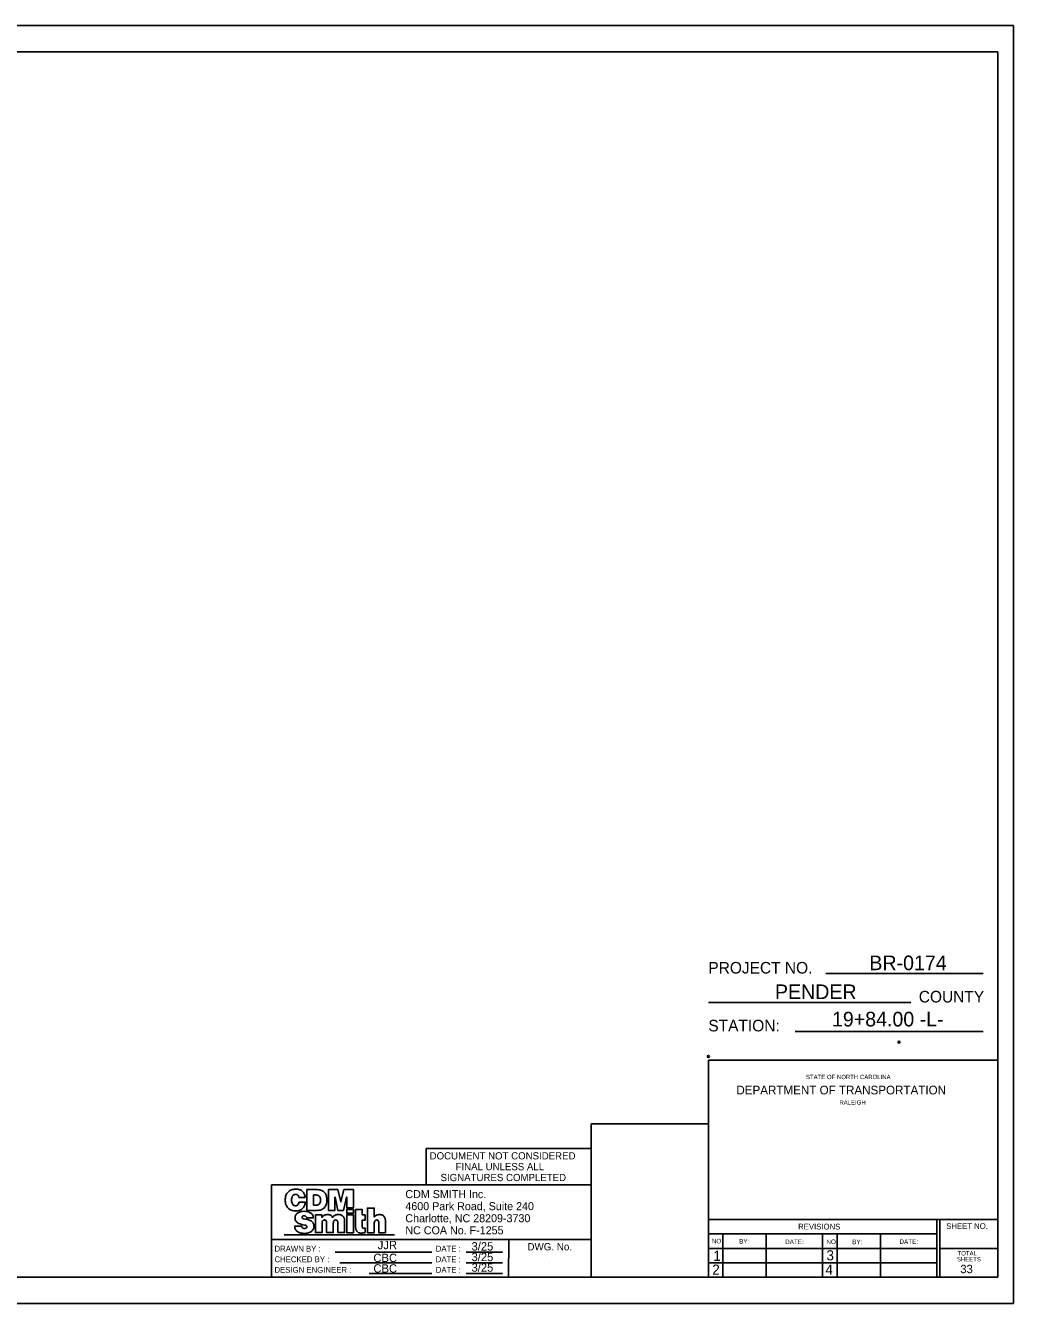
# Model space of a CAD drawing. Extents: x 0 to 2.83, y 0 to 1.83.
# Drawn here: x 1.417 to 2.833, y 0 to 1.833 of the extents above; entities that cross this region are included whole.
import ezdxf

# ---------------------------------------------------------------- set-up
doc = ezdxf.new("R2010")
doc.units = 0
for name, color, linetype in [('Default', 7, 'Continuous'), ('Old_Level_18', 7, 'Continuous'), ('Old_Level_19', 7, 'Continuous'), ('Plan Sheet', 7, 'Continuous'), ('Plan Sheet CELL', 7, 'Continuous'), ('Plot Shape CELL', 7, 'Continuous'), ('Scratch_Level_5', 7, 'Continuous'), ('Sheet Block Title CELL', 7, 'Continuous'), ('Sheet Plan CELL', 7, 'Continuous'), ('Sheet Sticker Exception Certification CELL', 7, 'Continuous'), ('SMU_Text', 7, 'Continuous'), ('z - Construction', 7, 'Continuous')]:
    doc.layers.add(name, color=color, linetype=linetype)

msp = doc.modelspace()

# ---------------------------------------------------------------- linework, layer by layer
at = {"layer": 'Plan Sheet'}
for p, q in [((2.2277, 0.0375), (2.2277, 0.2579)), ((2.2277, 0.2579), (2.3958, 0.2579)), ((1.7692, 0.1702), (2.2277, 0.1702)), ((1.7692, 0.0377), (1.7692, 0.1702)), ((1.7692, 0.0916), (2.2277, 0.0916)), ((1.8604, 0.0734), (1.9993, 0.0734)), ((2.0483, 0.0734), (2.1004, 0.0734)), ((2.1096, 0.0916), (2.1093, 0.0376)), ((1.9993, 0.0582), (1.8673, 0.0582)), ((2.0483, 0.0582), (2.1004, 0.0582)), ((2.2277, 0.0377), (1.769, 0.0377)), ((1.9094, 0.043), (1.9992, 0.043)), ((2.0483, 0.043), (2.1004, 0.043))]:
    msp.add_line(p, q, dxfattribs=at)
at = {"layer": 'Plan Sheet CELL'}
for p, q in [((2.79, 0.4733), (2.5645, 0.4733)), ((2.6863, 0.4318), (2.3958, 0.4318)), ((2.79, 0.3903), (2.5202, 0.3903)), ((2.8107, 0.3488), (2.3958, 0.3488)), ((2.3958, 0.3488), (2.3958, 0.0375)), ((2.3958, 0.1205), (2.8107, 0.1205)), ((2.7236, 0.1205), (2.7236, 0.0375)), ((2.7278, 0.1205), (2.7278, 0.0375)), ((2.3958, 0.0998), (2.7238, 0.0998)), ((2.396, 0.0998), (2.396, 0.0375)), ((2.4165, 0.0998), (2.4165, 0.0375)), ((2.4787, 0.0994), (2.4787, 0.0372)), ((2.5597, 0.0998), (2.5597, 0.037)), ((2.5805, 0.0998), (2.5805, 0.0374)), ((2.6428, 0.0998), (2.6428, 0.0374)), ((2.3958, 0.079), (2.7245, 0.079)), ((2.7278, 0.079), (2.81, 0.079)), ((2.3958, 0.0583), (2.7238, 0.0583)), ((2.7442, 0), (2.7442, 0))]:
    msp.add_line(p, q, dxfattribs=at)
at = {"layer": 'Plot Shape CELL'}
msp.add_lwpolyline([(0, 1.8333), (2.8333, 1.8333), (2.8333, 0), (0, 0)], close=True, dxfattribs=at)
at = {"layer": 'Scratch_Level_5'}
msp.add_line((2.1684, 0.0568), (2.1684, 0.0568), dxfattribs=at)
for centre in [(2.6692, 0.3747), (2.3958, 0.3543)]:
    msp.add_circle(centre, 0.00141, dxfattribs=at)
at = {"layer": 'Sheet Block Title CELL'}
msp.add_line((1.7876, 0.0982), (1.9457, 0.0982), dxfattribs=at)
for points in [[(1.7993, 0.1427), (1.799, 0.1433), (1.7988, 0.144), (1.7984, 0.1454), (1.7982, 0.1468), (1.7981, 0.1483), (1.7982, 0.1499), (1.7984, 0.1513), (1.7988, 0.1527), (1.799, 0.1533), (1.7993, 0.1539), (1.7997, 0.1545), (1.8001, 0.155), (1.8005, 0.1554), (1.8012, 0.1559), (1.8017, 0.1562), (1.8024, 0.1564), (1.8031, 0.1565), (1.8038, 0.1566), (1.8045, 0.1565), (1.8051, 0.1564), (1.8056, 0.1563), (1.8061, 0.1561), (1.8067, 0.1558), (1.807, 0.1554), (1.8076, 0.1547), (1.8081, 0.154), (1.8084, 0.1533), (1.8086, 0.1526), (1.8087, 0.1522), (1.8176, 0.1522), (1.8174, 0.1535), (1.8171, 0.1548), (1.8168, 0.1561), (1.8163, 0.1572), (1.8158, 0.1582), (1.8152, 0.1592), (1.8145, 0.1601), (1.8137, 0.1608), (1.8128, 0.1615), (1.8117, 0.1623), (1.8107, 0.1628), (1.8096, 0.1632), (1.8083, 0.1636), (1.807, 0.1638), (1.8055, 0.164), (1.8041, 0.164), (1.8024, 0.164), (1.8008, 0.1637), (1.7992, 0.1634), (1.7978, 0.1629), (1.7965, 0.1623), (1.7953, 0.1615), (1.794, 0.1606), (1.793, 0.1597), (1.7921, 0.1586), (1.7913, 0.1575), (1.7906, 0.1562), (1.79, 0.1547), (1.7895, 0.1533), (1.7892, 0.1517), (1.789, 0.1501), (1.7889, 0.1483), (1.789, 0.1467), (1.7892, 0.1451), (1.7895, 0.1435), (1.7899, 0.1421), (1.7905, 0.1408), (1.7911, 0.1395), (1.7919, 0.1383), (1.7928, 0.1371), (1.7938, 0.1361), (1.7951, 0.1353), (1.7963, 0.1345), (1.7976, 0.1339), (1.799, 0.1334), (1.8007, 0.133), (1.8023, 0.1328), (1.8041, 0.1327), (1.8056, 0.1327), (1.8072, 0.133), (1.8086, 0.1333), (1.8099, 0.1338), (1.8111, 0.1343), (1.8122, 0.135), (1.8133, 0.1357), (1.8142, 0.1366), (1.815, 0.1375), (1.8157, 0.1385), (1.8163, 0.1396), (1.8168, 0.1406), (1.8172, 0.1417), (1.8175, 0.1428), (1.8177, 0.144), (1.8177, 0.1451), (1.8087, 0.1451), (1.8085, 0.1441), (1.8082, 0.1431), (1.8078, 0.1423), (1.8073, 0.1415), (1.8065, 0.1409), (1.8058, 0.1405), (1.8049, 0.1402), (1.8038, 0.1401), (1.8031, 0.1402), (1.8024, 0.1403), (1.8017, 0.1405), (1.8012, 0.1408), (1.8005, 0.1412), (1.8001, 0.1416), (1.7997, 0.1421), (1.7993, 0.1427)], [(1.8489, 0.1467), (1.8489, 0.1483), (1.8489, 0.1497), (1.8488, 0.1512), (1.8484, 0.1526), (1.8481, 0.1539), (1.8477, 0.1551), (1.8472, 0.1565), (1.8466, 0.1576), (1.8459, 0.1587), (1.845, 0.1597), (1.8441, 0.1605), (1.843, 0.1613), (1.8417, 0.1621), (1.8403, 0.1626), (1.8388, 0.163), (1.8372, 0.1632), (1.8353, 0.1633), (1.8202, 0.1633), (1.8202, 0.1334), (1.8336, 0.1334), (1.8354, 0.1334), (1.8373, 0.1336), (1.8389, 0.134), (1.8404, 0.1344), (1.8417, 0.135), (1.8431, 0.1357), (1.8442, 0.1365), (1.8452, 0.1374), (1.846, 0.1385), (1.8468, 0.1396), (1.8474, 0.1408), (1.8479, 0.1421), (1.8483, 0.1435), (1.8486, 0.1451), (1.8489, 0.1467)], [(1.8294, 0.1556), (1.8324, 0.1556), (1.8336, 0.1555), (1.8346, 0.1554), (1.8355, 0.1551), (1.8363, 0.1547), (1.8371, 0.1543), (1.8377, 0.1538), (1.8381, 0.1533), (1.8385, 0.1528), (1.8389, 0.1522), (1.8391, 0.1516), (1.8395, 0.1504), (1.8396, 0.1493), (1.8397, 0.1485), (1.8396, 0.1474), (1.8394, 0.1462), (1.8391, 0.1449), (1.8388, 0.1443), (1.8385, 0.1437), (1.8382, 0.1431), (1.8377, 0.1426), (1.8372, 0.1422), (1.8365, 0.1418), (1.8358, 0.1415), (1.835, 0.1412), (1.8341, 0.1411), (1.8331, 0.141), (1.8294, 0.141), (1.8294, 0.1556)], [(1.8603, 0.1526), (1.8605, 0.1526), (1.8646, 0.1334), (1.8727, 0.1334), (1.8771, 0.1526), (1.8773, 0.1526), (1.8773, 0.1371), (1.8868, 0.1371), (1.8868, 0.1633), (1.8732, 0.1633), (1.8689, 0.1457), (1.8688, 0.1457), (1.8645, 0.1633), (1.851, 0.1633), (1.851, 0.1334), (1.8603, 0.1334), (1.8603, 0.1526)], [(1.8301, 0.112), (1.83, 0.1128), (1.8298, 0.1135), (1.8296, 0.1144), (1.8293, 0.115), (1.829, 0.1156), (1.8286, 0.1162), (1.8282, 0.1167), (1.8272, 0.1176), (1.8261, 0.1184), (1.825, 0.119), (1.8236, 0.1195), (1.8223, 0.12), (1.821, 0.1203), (1.8183, 0.1209), (1.8161, 0.1213), (1.8152, 0.1216), (1.8144, 0.1219), (1.814, 0.1221), (1.8136, 0.1224), (1.8133, 0.1228), (1.8132, 0.1234), (1.8133, 0.1241), (1.8135, 0.1246), (1.8138, 0.125), (1.8142, 0.1253), (1.8147, 0.1255), (1.8153, 0.1256), (1.8164, 0.1258), (1.817, 0.1256), (1.8176, 0.1255), (1.8181, 0.1252), (1.8187, 0.1248), (1.8192, 0.1244), (1.8196, 0.1239), (1.8198, 0.1233), (1.8199, 0.1226), (1.8294, 0.1226), (1.8293, 0.124), (1.829, 0.1252), (1.8286, 0.1264), (1.8281, 0.1274), (1.8274, 0.1282), (1.8267, 0.129), (1.8259, 0.1297), (1.8249, 0.1302), (1.8239, 0.1307), (1.8228, 0.1311), (1.8218, 0.1314), (1.8207, 0.1318), (1.8195, 0.132), (1.8183, 0.1321), (1.8161, 0.1322), (1.814, 0.1321), (1.8129, 0.1319), (1.8117, 0.1318), (1.8106, 0.1314), (1.8096, 0.1311), (1.8086, 0.1307), (1.8076, 0.1302), (1.8067, 0.1296), (1.8057, 0.1289), (1.805, 0.1281), (1.8044, 0.1273), (1.8039, 0.1263), (1.8035, 0.1251), (1.8032, 0.1239), (1.8031, 0.1225), (1.8032, 0.1216), (1.8033, 0.1207), (1.8035, 0.1199), (1.8038, 0.119), (1.8041, 0.1183), (1.8046, 0.1176), (1.8051, 0.117), (1.8057, 0.1164), (1.8064, 0.1159), (1.8073, 0.1154), (1.8082, 0.1149), (1.8092, 0.1145), (1.8103, 0.1141), (1.8115, 0.1136), (1.8144, 0.113), (1.8173, 0.1124), (1.8183, 0.1121), (1.8191, 0.1118), (1.8196, 0.1114), (1.8199, 0.111), (1.8201, 0.1105), (1.8202, 0.1099), (1.8201, 0.1093), (1.8198, 0.1088), (1.8194, 0.1084), (1.8189, 0.1081), (1.8183, 0.1079), (1.8177, 0.1076), (1.8166, 0.1075), (1.8157, 0.1076), (1.8149, 0.1078), (1.8143, 0.1081), (1.8138, 0.1084), (1.8133, 0.109), (1.8129, 0.1097), (1.8127, 0.1103), (1.8125, 0.1111), (1.8025, 0.1111), (1.8026, 0.1097), (1.8029, 0.1084), (1.8033, 0.1072), (1.8038, 0.1061), (1.8044, 0.1052), (1.8052, 0.1043), (1.806, 0.1035), (1.807, 0.1029), (1.808, 0.1023), (1.8091, 0.1018), (1.8102, 0.1013), (1.8113, 0.101), (1.8125, 0.1007), (1.8138, 0.1006), (1.815, 0.1005), (1.8162, 0.1004), (1.8188, 0.1005), (1.82, 0.1007), (1.8212, 0.1009), (1.8224, 0.1012), (1.8235, 0.1016), (1.8246, 0.1021), (1.8257, 0.1027), (1.8267, 0.1033), (1.8275, 0.1041), (1.8283, 0.1049), (1.8289, 0.1059), (1.8294, 0.107), (1.8298, 0.1083), (1.8301, 0.1096), (1.8301, 0.1111), (1.8301, 0.112)], [(1.8868, 0.1346), (1.8773, 0.1346), (1.8773, 0.1294), (1.8868, 0.1294), (1.8868, 0.1346)], [(1.9036, 0.1269), (1.8994, 0.1269), (1.8994, 0.1346), (1.89, 0.1346), (1.89, 0.1269), (1.89, 0.1197), (1.89, 0.1109), (1.89, 0.109), (1.8902, 0.1072), (1.8905, 0.1058), (1.891, 0.1046), (1.8915, 0.1037), (1.892, 0.103), (1.8927, 0.1025), (1.8934, 0.102), (1.8943, 0.1015), (1.8954, 0.1012), (1.8967, 0.101), (1.8984, 0.101), (1.8995, 0.101), (1.9008, 0.1012), (1.9022, 0.1014), (1.9036, 0.1019), (1.9036, 0.1082), (1.9032, 0.1081), (1.9024, 0.108), (1.901, 0.1079), (1.9005, 0.108), (1.9001, 0.1083), (1.8999, 0.1085), (1.8997, 0.1087), (1.8996, 0.109), (1.8995, 0.1095), (1.8994, 0.1108), (1.8994, 0.1197), (1.9036, 0.1197), (1.9036, 0.1269)], [(1.9323, 0.122), (1.9319, 0.1229), (1.9316, 0.1237), (1.9311, 0.1244), (1.9306, 0.125), (1.93, 0.1256), (1.9294, 0.1261), (1.9287, 0.1265), (1.9279, 0.1269), (1.9271, 0.1271), (1.9262, 0.1273), (1.9253, 0.1274), (1.9244, 0.1275), (1.9232, 0.1274), (1.9221, 0.1273), (1.921, 0.1271), (1.9197, 0.1266), (1.9189, 0.1261), (1.9182, 0.1255), (1.9174, 0.1248), (1.9166, 0.124), (1.9166, 0.1368), (1.9068, 0.1368), (1.9068, 0.1015), (1.9166, 0.1015), (1.9166, 0.1137), (1.9166, 0.1153), (1.9168, 0.1167), (1.9172, 0.1177), (1.9174, 0.1181), (1.9176, 0.1185), (1.918, 0.119), (1.9186, 0.1194), (1.9192, 0.1197), (1.9198, 0.1198), (1.9206, 0.1198), (1.9213, 0.1196), (1.9218, 0.1193), (1.9223, 0.1188), (1.9227, 0.1183), (1.9229, 0.1175), (1.9231, 0.1166), (1.9231, 0.1155), (1.9231, 0.1015), (1.9328, 0.1015), (1.9328, 0.1176), (1.9328, 0.1188), (1.9327, 0.12), (1.9325, 0.1211), (1.9323, 0.122)], [(1.8421, 0.1171), (1.8423, 0.1178), (1.8428, 0.1185), (1.8432, 0.119), (1.8437, 0.1194), (1.8444, 0.1197), (1.8453, 0.1199), (1.8462, 0.1197), (1.847, 0.1194), (1.8475, 0.119), (1.8479, 0.1184), (1.8481, 0.1177), (1.8483, 0.117), (1.8484, 0.1162), (1.8484, 0.1153), (1.8484, 0.1016), (1.858, 0.1016), (1.858, 0.1153), (1.8581, 0.1162), (1.8582, 0.1171), (1.8584, 0.1178), (1.8588, 0.1185), (1.8592, 0.119), (1.8597, 0.1194), (1.8604, 0.1197), (1.8614, 0.1199), (1.8623, 0.1197), (1.8631, 0.1194), (1.8636, 0.119), (1.864, 0.1184), (1.8642, 0.1177), (1.8644, 0.117), (1.8645, 0.1162), (1.8645, 0.1153), (1.8645, 0.1016), (1.8741, 0.1016), (1.8741, 0.1189), (1.874, 0.1205), (1.8739, 0.1213), (1.8737, 0.122), (1.8735, 0.1227), (1.8731, 0.1234), (1.8726, 0.1241), (1.8722, 0.1247), (1.8716, 0.1253), (1.871, 0.1259), (1.8703, 0.1264), (1.8695, 0.1268), (1.8687, 0.1271), (1.8677, 0.1273), (1.8666, 0.1275), (1.8654, 0.1275), (1.8643, 0.1275), (1.8633, 0.1274), (1.8624, 0.1272), (1.8615, 0.127), (1.8608, 0.1267), (1.86, 0.1264), (1.8589, 0.1256), (1.8581, 0.1249), (1.8575, 0.1243), (1.8569, 0.1235), (1.8563, 0.1244), (1.8557, 0.1252), (1.8549, 0.126), (1.854, 0.1265), (1.853, 0.1269), (1.8521, 0.1273), (1.8511, 0.1275), (1.85, 0.1275), (1.8488, 0.1275), (1.8475, 0.1273), (1.8464, 0.127), (1.8453, 0.1266), (1.8443, 0.1261), (1.8434, 0.1253), (1.8425, 0.1245), (1.8416, 0.1234), (1.8416, 0.1269), (1.8324, 0.1269), (1.8324, 0.1016), (1.8419, 0.1016), (1.8419, 0.1153), (1.842, 0.1162), (1.8421, 0.1171)], [(1.8868, 0.1269), (1.8773, 0.1269), (1.8773, 0.1015), (1.8868, 0.1015), (1.8868, 0.1269)]]:
    msp.add_lwpolyline(points, dxfattribs=at)
at = {"layer": 'Sheet Plan CELL'}
for p, q in [((2.8108, 1.7958), (0.0608, 1.7958)), ((2.8107, 0.0375), (2.8108, 1.7958)), ((0.0607, 0.0375), (2.8107, 0.0375))]:
    msp.add_line(p, q, dxfattribs=at)
at = {"layer": 'Sheet Sticker Exception Certification CELL'}
msp.add_lwpolyline([(1.9913, 0.2223), (2.2277, 0.2223), (2.2277, 0.1702), (1.9913, 0.1702)], close=True, dxfattribs=at)
at = {"layer": 'z - Construction'}
for p, q in [((2.8333, 1.8333), (0, 1.8333)), ((2.8333, 0), (2.8333, 1.8333)), ((0, 0), (2.8333, 0))]:
    msp.add_line(p, q, dxfattribs=at)

# ---------------------------------------------------------------- texts
at = {"layer": 'Default'}
for s, p in [('CDM SMITH Inc.', (1.9613, 0.1511)), ('4600 Park Road, Suite 240', (1.9613, 0.1338)), ('Charlotte, NC 28209-3730', (1.9613, 0.1165)), ('NC COA No. F-1255', (1.9613, 0.0992))]:
    msp.add_text(s, height=0.011482, dxfattribs=at).set_placement(p)
at = {"layer": 'Old_Level_18'}
msp.add_text('19+84.00 -L-', height=0.021, dxfattribs=at).set_placement((2.5731, 0.3974))
at = {"layer": 'Old_Level_19'}
for s, p in [('BR-0174', (2.6267, 0.4781)), ('PENDER', (2.4913, 0.4366))]:
    msp.add_text(s, height=0.021, dxfattribs=at).set_placement(p)
at = {"layer": 'Plan Sheet'}
for s, height, p in [('DRAWN BY :', 0.00833, (1.7736, 0.0744)), ('DATE :', 0.00833, (2.0049, 0.0744)), ('DWG. No.', 0.0105, (2.1364, 0.0761)), ('CHECKED BY :', 0.008333, (1.7736, 0.0592)), ('DATE :', 0.00833, (2.0049, 0.0592)), ('33', 0.012, (2.7572, 0.0434)), ('DESIGN ENGINEER :', 0.008333, (1.7736, 0.044)), ('DATE :', 0.00833, (2.0049, 0.044))]:
    msp.add_text(s, height=height, dxfattribs=at).set_placement(p)
at = {"layer": 'Plan Sheet CELL'}
for s, height, p in [('PROJECT NO.', 0.0166, (2.3958, 0.4733)), ('COUNTY', 0.0166, (2.6976, 0.4318)), ('STATION:', 0.0166, (2.3958, 0.3903)), ('DEPARTMENT OF TRANSPORTATION', 0.01245, (2.436, 0.2999)), ('STATE OF NORTH CAROLINA', 0.006225, (2.5358, 0.3218)), ('RALEIGH', 0.00622, (2.5837, 0.2853)), ('REVISIONS', 0.0083, (2.5246, 0.1061)), ('SHEET NO.', 0.0083, (2.7369, 0.1068)), ('NO.', 0.00661, (2.4007, 0.0861)), ('BY:', 0.00661, (2.4399, 0.0858)), ('DATE:', 0.00661, (2.5058, 0.0851)), ('NO.', 0.00661, (2.565, 0.0851)), ('DATE:', 0.00661, (2.6698, 0.0854)), ('1', 0.0145, (2.4029, 0.0611)), ('3', 0.0145, (2.5652, 0.0618)), ('BY:', 0.00661, (2.6021, 0.085)), ('TOTAL', 0.00622, (2.7532, 0.0688)), ('2', 0.0145, (2.4014, 0.0413)), ('4', 0.0145, (2.5636, 0.0413)), ('SHEETS', 0.00622, (2.7522, 0.0604))]:
    msp.add_text(s, height=height, dxfattribs=at).set_placement(p)
at = {"layer": 'Sheet Sticker Exception Certification CELL'}
for s, p in [('DOCUMENT NOT CONSIDERED', (1.9961, 0.2066)), ('SIGNATURES COMPLETED', (2.0118, 0.1755)), ('FINAL UNLESS ALL', (2.0333, 0.1911))]:
    msp.add_text(s, height=0.010352, dxfattribs=at).set_placement(p)
at = {"layer": 'SMU_Text'}
for s, p in [('JJR', (1.9217, 0.0778)), ('3/25', (2.0562, 0.0759)), ('3/25', (2.0562, 0.0607)), ('CBC', (1.9155, 0.0594)), ('CBC', (1.9155, 0.0442)), ('3/25', (2.0562, 0.0455))]:
    msp.add_text(s, height=0.012, dxfattribs=at).set_placement(p)

doc.saveas('drawing.dxf')
